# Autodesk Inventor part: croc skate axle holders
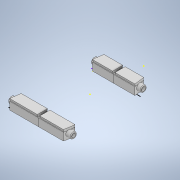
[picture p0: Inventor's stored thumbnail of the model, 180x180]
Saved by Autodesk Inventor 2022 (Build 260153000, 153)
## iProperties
Created: 2021-07
Part Number: croc skate axle holders
Material: Generic
Document SubType Name: Modeling
Designer: garre
Density: 1 g/cm^3
Appearance: Default
Author: garre
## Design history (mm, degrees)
sketch "Sketch1"
  geometry: L1 (-71.087, 225.965)-(81.313, 225.965); L2 (81.313, 225.965)-(81.313, 204.375); L3 (81.313, 204.375)-(-71.087, 204.375); L4 (-71.087, 204.375)-(-71.087, 225.965); L5 (-57.295, 64.261)-(64.925, 64.261); L6 (64.925, 64.261)-(64.925, 42.671); L7 (64.925, 42.671)-(-57.295, 42.671); L8 (-57.295, 42.671)-(-57.295, 64.261); L9 (6.54, -0.509)-(57.34, -0.509) reference; L10 (23.796, 300.895)-(0, 300.895) reference; L11 (0, 0)-(0, 315.601) reference; L12 (2.54, 300.895)-(-2.54, 300.895); L13 (-2.54, 300.895)-(-2.54, -5.952); L14 (-2.54, -5.952)-(2.54, -5.952); L15 (2.54, -5.952)-(2.54, 300.895); 32 further points
  constraints: 30 end point, 7 horizontal, 6 parallel, 3 perpendicular, 2 vertical, 1 point on line, 15 other
  dimensions: "d0" = 21.59 distance of L1.end L2.end; "d1" = 152.4 distance of L2.end L3.end; "d2" = 21.59 distance of L5.end L6.end; "d3" = 50.8 distance of L9.start L9.end; "d4" = 43.18 distance between parallel lines of L9 L7; "d5" = 74.93 distance between parallel lines of L10 L1; "d6" = 5.08 distance between parallel lines of L13 L15; "d7" = 2.54 distance between parallel lines of L11 L13; "d61" = 61.15095 distance from line of L15 point (63.691, 251.973)
extrude "Extrusion5" new body sketch "Sketch1" distance "d23" = 16.51; taper "d24" = 0 deg
sketch "Sketch7"
  geometry: L1 (-2.54, -204.375)-(-59.142, -204.375) reference; L2 (-62.162, -225.965)-(-2.54, -225.965) reference; L3 (-2.54, -225.965)-(-2.54, -204.375) reference; L4 (2.54, -225.965)-(53.089, -225.965) reference; L5 (56.386, -204.375)-(2.54, -204.375) reference; L6 (2.54, -204.375)-(2.54, -225.965) reference; L7 (2.54, -64.261)-(45.11, -64.261) reference; L8 (42.338, -42.671)-(2.54, -42.671) reference; L9 (2.54, -42.671)-(2.54, -64.261) reference; L10 (-2.54, -42.671)-(-42.735, -42.671) reference; L11 (-45.688, -64.261)-(-2.54, -64.261) reference; L12 (-2.54, -64.261)-(-2.54, -42.671) reference; L13 (-2.54, -225.965)-(-2.54, -204.375) reference; L14 (-2.54, -224.695)-(-62.024, -224.695); L15 (-2.54, -205.645)-(-59.357, -205.645); L16 (2.54, -204.375)-(2.54, -225.965) reference; L17 (2.54, -224.695)-(53.4, -224.695); L18 (2.54, -205.645)-(56.303, -205.645); L19 (-2.54, -64.261)-(-2.54, -42.671) reference; L20 (-2.54, -62.991)-(-45.582, -62.991); L21 (-2.54, -43.941)-(-42.986, -43.941); L22 (2.54, -42.671)-(2.54, -64.261) reference; L23 (2.54, -62.991)-(45.029, -62.991); L24 (2.54, -43.941)-(42.609, -43.941); 8 further points
  constraints: 16 end point, 11 point on line, 4 parallel, 3 perpendicular, 12 other
  dimensions: "d25" = 1.27 distance between parallel lines of L2 L14; "d26" = 1.27 distance between parallel lines of L1 L15; "d27" = 1.27 distance between parallel lines of L5 L18; "d28" = 1.27 distance between parallel lines of L4 L17; "d29" = 1.27 distance between parallel lines of L11 L20; "d30" = 1.27 distance between parallel lines of L10 L21
extrude "Extrusion6" join sketch "Sketch7" distance "d31" = 5.08; taper "d32" = 0 deg
feature "FaceDraft1" dims angle "d33" = 15 deg
feature "FaceDraft2" dims angle "d34" = 15 deg
sketch "Sketch8"
  geometry: L1 (-161.795, 21.59)-(-140.023, 21.59) reference; L2 (-161.704, 0)-(-140.114, 0) reference; L3 (-140.114, 0)-(-140.114, 16.51) reference; L4 (0, 0)-(0, 16.51) reference; L5 (-0.091, 21.59)-(21.681, 21.59) reference; C1 r 4.064 at (-150.909, 10.795); C2 r 4.064 at (10.795, 10.795); 1 further point
  constraints: 2 centre point
  dimensions: "d35" = 8.128 diameter of C1; "d36" = 8.128 diameter of C2; "d37" = 10.795 distance from line of L1 C1.centre; "d38" = 10.795 distance from line of L2 C1.centre (derived); "d39" = 10.795 distance from line of L3 C1.centre; "d40" = 10.795 distance from line of L4 C2.centre; "d41" = 10.795 distance from line of L5 C2.centre
extrude "Extrusion7" cut sketch "Sketch8" stored distance "d42" = 177.8; taper "d43" = 0 deg
sketch "Sketch9"
  geometry: C1 r 4.064 at (10.795, 10.795) reference; C2 r 6.604 at (10.795, 10.795); C3 r 4.064 at (10.795, 10.795); C4 r 4.064 at (-150.909, 10.795) reference; C5 r 4.064 at (-150.909, 10.795); C6 r 6.604 at (-150.909, 10.795); 1 further point
  constraints: 4 centre point, 4 coincident
  dimensions: "d44" = 13.208 diameter of C2; "d45" = 13.208 diameter of C6
extrude "Extrusion8" join sketch "Sketch9" distance "d46" = 62.23; taper "d47" = 0 deg
sketch "Sketch10"
  geometry: C1 r 4.064 at (10.795, 10.795) reference; C2 r 6.604 at (10.795, 10.795); C3 r 4.064 at (10.795, 10.795); 1 further point
  constraints: 2 centre point, 2 coincident
  dimensions: "d48" = 13.208 diameter of C2
extrude "Extrusion9" join sketch "Sketch10" distance "d49" = 50.8; taper "d50" = 0 deg
sketch "Sketch11"
  geometry: C1 r 4.064 at (10.795, 10.795) reference; C2 r 4.064 at (10.795, 10.795); C3 r 6.604 at (10.795, 10.795); 1 further point
  constraints: 2 centre point, 2 coincident
  dimensions: "d51" = 13.208 diameter of C3
extrude "Extrusion10" join sketch "Sketch11" distance "d52" = 50.8; taper "d53" = 0 deg
sketch "Sketch12"
  geometry: C1 r 6.604 at (10.795, 10.795) reference; C2 r 4.064 at (10.795, 10.795); C3 r 6.604 at (10.795, 10.795); 1 further point
  constraints: 2 centre point, 2 coincident
  dimensions: "d54" = 13.208 diameter of C3
extrude "Extrusion11" join sketch "Sketch12" distance "d55" = 67.31; taper "d56" = 0 deg
fillet "Fillet2" dims "d58" = 1.27
sketch "Sketch13"
  geometry: L1 (0, -260.751)-(0, 0); L2 (-81.985, -142.779)-(74.163, -142.779)
  constraints: 4 end point, 1 horizontal, 1 vertical
split "Split1" sketch "Sketch13"
  body "Solid2"
sketch "Sketch14"
  geometry: L1 (-81.263, -137.266)-(76.644, -137.266); 1 further point
  constraints: 2 end point, 1 horizontal
  dimensions: "d59" = 137.26581 distance from line of L1 point (0, 0)
split "Split2" sketch "Sketch14"
  body "Solid4"
sketch "Sketch15"
  geometry: L1 (-81.551, -148.524)-(58.168, -148.524); 1 further point
  constraints: 2 end point, 1 horizontal
  dimensions: "d60" = 148.5242 distance from line of L1 point (0, 0)
split "Split3" sketch "Sketch15"
  body "Solid3"
sketch "Sketch16"
  geometry: L1 (-61.685, 221.774)-(-68.58, 221.774) reference; L2 (-61.685, 221.774)-(-69.813, 221.774); L3 (44.814, 60.07)-(52.07, 60.07) reference; L4 (44.814, 60.07)-(53.183, 60.07); L5 (-45.309, 60.07)-(-53.223, 60.07); 4 further points; 1 other entity
  constraints: 6 end point, 2 horizontal, 2 point on line, 1 collinear, 2 other
sketch "Sketch18"
  geometry: L1 (0, 0)-(0, 16.51) reference; L2 (21.59, 0)-(21.59, 16.51) reference; L3 (0, 16.51)-(21.59, 16.51); L4 (21.59, 16.51)-(21.59, 0); L5 (21.59, 0)-(0, 0); L6 (0, 0)-(0, 16.51); C1 r 4.064 at (10.795, 10.795) reference; C2 r 4.064 at (10.795, 10.795); 3 further points
  constraints: 8 end point, 2 parallel, 1 centre point, 1 coincident, 1 horizontal, 1 perpendicular
extrude "Extrusion12" join sketch "Sketch18" distance "d62" = 2.54; taper "d63" = 0 deg
sketch "Sketch19"
  geometry: L1 (0, 0)-(0, 16.51) reference; L2 (21.59, 0)-(21.59, 16.51) reference; L3 (0, 0)-(21.59, 0); L4 (21.59, 0)-(21.59, 16.51); L5 (21.59, 16.51)-(0, 16.51); L6 (0, 16.51)-(0, 0); C1 r 4.064 at (10.795, 10.795) reference; C2 r 4.064 at (10.795, 10.795); 3 further points
  constraints: 8 end point, 2 parallel, 1 centre point, 1 coincident, 1 horizontal, 1 perpendicular
extrude "Extrusion13" join sketch "Sketch19" distance "d64" = 2.54; taper "d65" = 0 deg
sketch "Sketch20"
  geometry: L1 (0, 0)-(0, 16.51) reference; L2 (21.59, 0)-(21.59, 16.51) reference; L3 (0, 0)-(21.59, 0); L4 (21.59, 0)-(21.59, 16.51); L5 (21.59, 16.51)-(0, 16.51); L6 (0, 16.51)-(0, 0); C1 r 4.064 at (10.795, 10.795) reference; C2 r 4.064 at (10.795, 10.795); 3 further points
  constraints: 8 end point, 2 parallel, 1 centre point, 1 coincident, 1 horizontal, 1 perpendicular
extrude "Extrusion14" join sketch "Sketch20" distance "d66" = 2.54; taper "d67" = 0 deg
sketch "Sketch21"
  geometry: L1 (21.59, 0)-(21.59, 16.51) reference; L2 (0, 0)-(0, 16.51) reference; L3 (21.59, 16.51)-(0, 16.51); L4 (0, 16.51)-(0, 0); L5 (0, 0)-(21.59, 0); L6 (21.59, 0)-(21.59, 16.51); C1 r 4.064 at (10.795, 10.795) reference; C2 r 4.064 at (10.795, 10.795); 3 further points
  constraints: 8 end point, 2 parallel, 1 centre point, 1 coincident, 1 horizontal, 1 perpendicular
extrude "Extrusion15" join sketch "Sketch21" distance "d68" = 2.54; taper "d69" = 0 deg
node "Projected Loop13"
node "Projected Loop14"
node "Projected Loop15"
node "Projected Loop16"
node "back outside"
node "front outside"
node "back inside"
node "front inside"
